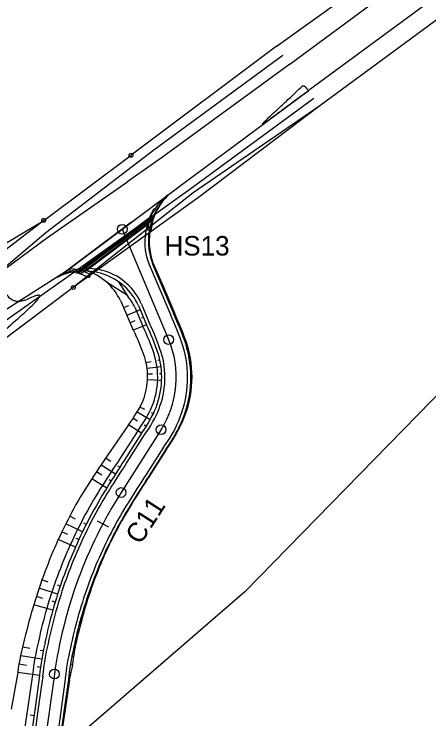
# Model space of a CAD drawing. Extents: x -495905 to -478420, y -1113297 to -1107716.
# Drawn here: x -481613 to -481549.1, y -1112614.7 to -1112506 of the extents above; entities that cross this region are included whole.
import ezdxf

# ---------------------------------------------------------------- set-up
doc = ezdxf.new("R2010")
doc.units = 0
for name, color, linetype in [('03_PC_OBJEKTY_STAV', 7, 'Continuous'), ('03_PC_POPIS_NÁVRH', 7, 'Continuous'), ('2D_VRSTEVNICE', 7, 'Continuous'), ('C11_HATCH_SLOPE_L', 7, 'Continuous'), ('C11_HATCH_SLOPE_R', 7, 'Continuous'), ('C11_HECTOMETRY', 7, 'Continuous'), ('C11_HLBODY', 7, 'Continuous'), ('C11_HRANA_TELESO', 7, 'Continuous'), ('C11_KORUNA', 7, 'Continuous'), ('C11_OSA', 7, 'Continuous'), ('C11_PRIKOP', 7, 'Continuous'), ('C11_STANICENI', 7, 'Continuous'), ('C11_VOZOVKA', 7, 'Continuous'), ('C11_ZPEVKRAJ', 7, 'Continuous'), ('křižovatky', 7, 'Continuous'), ('ODVODNĚNÍ PLOŠNÉ', 7, 'Continuous'), ('PLYN', 7, 'Continuous'), ('pomoc', 7, 'Continuous'), ('zamereni', 7, 'Continuous'), ('ŽLAB', 7, 'Continuous')]:
    doc.layers.add(name, color=color, linetype=linetype)

# ---------------------------------------------------------------- blocks, each defined once
blk = doc.blocks.new('A$C55D')
at = {"layer": 'ŽLAB'}
for p, q in [((-7.761, 0.901), (-8.121, 0.554)), ((-8.121, 0.554), (-7.1, -0.505)), ((-6.608, -0.294), (-7.761, 0.901)), ((-6.75, -0.147), (6.75, 0.147)), ((6.456, -0.009), (8.142, 0.887)), ((7.567, 0.015), (6.708, -0.004)), ((8.377, 0.446), (7.174, -0.193)), ((8.142, 0.887), (8.377, 0.446)), ((6.708, -0.004), (-7.289, -0.309)), ((7.174, -0.193), (-7.1, -0.505)), ((-7.1, -0.505), (-6.174, -1.981)), ((-6.976, -0.703), (6.971, -0.398)), ((-5.75, -1.715), (-6.394, -0.69)), ((6.098, -0.567), (-6.301, -0.838)), ((5.398, -1.272), (6.251, -0.414)), ((7.174, -0.193), (5.752, -1.625)), ((-6.174, -1.981), (-5.75, -1.715)), ((5.752, -1.625), (5.398, -1.272))]:
    blk.add_line(p, q, dxfattribs=at)

msp = doc.modelspace()

# ---------------------------------------------------------------- linework, layer by layer
at = {"layer": '2D_VRSTEVNICE'}
for points in [[(-481647.93, -1112548.5), (-481648.61, -1112547.68), (-481664.2, -1112542.72), (-481664.55, -1112542.45), (-481665.56, -1112541.98), (-481665.08, -1112541.52), (-481663.7, -1112539.31), (-481651.29, -1112540.7), (-481629.73, -1112529.7), (-481626.86, -1112529.87), (-481616.46, -1112498.69), (-481609.21, -1112494.2)], [(-481568.62, -1112517.17), (-481572.56, -1112520.9), (-481572.83, -1112521.09), (-481575.41, -1112523.59), (-481572.64, -1112521.55), (-481572.56, -1112521.5), (-481567.66, -1112517.89), (-481567.59, -1112517.97), (-481568.31, -1112516.94), (-481568.62, -1112517.17)], [(-481610.72, -1112549.89), (-481614.2, -1112551.56), (-481614.87, -1112546.89)], [(-481624.37, -1112563.28), (-481623.78, -1112562.56), (-481623.64, -1112562.53), (-481623.56, -1112562.46), (-481618.52, -1112558.17), (-481617.34, -1112557.32), (-481616.73, -1112556.77), (-481606.97, -1112548.11), (-481610.72, -1112549.89)]]:
    msp.add_open_spline(points, degree=2, dxfattribs=at)
at = {"layer": 'C11_HATCH_SLOPE_L'}
for p, q in [((-481589.91, -1112548.7), (-481589.84, -1112548.67)), ((-481589.77, -1112548.65), (-481589.77, -1112548.65)), ((-481589.42, -1112549.85), (-481589.28, -1112549.8)), ((-481588.93, -1112551.01), (-481588.86, -1112550.98)), ((-481588.79, -1112550.95), (-481588.79, -1112550.95)), ((-481588.45, -1112552.16), (-481588.3, -1112552.1)), ((-481586.14, -1112558.41), (-481586.05, -1112558.39)), ((-481585.96, -1112558.37), (-481585.96, -1112558.37)), ((-481585.9, -1112559.82), (-481585.72, -1112559.8)), ((-481585.78, -1112561.25), (-481585.69, -1112561.25)), ((-481585.6, -1112561.25), (-481585.6, -1112561.25)), ((-481585.77, -1112562.69), (-481585.59, -1112562.7)), ((-481587.51, -1112569.61), (-481587.47, -1112569.63)), ((-481587.42, -1112569.65), (-481587.42, -1112569.65)), ((-481588.2, -1112570.87), (-481588.12, -1112570.92)), ((-481588.9, -1112571.99), (-481588.86, -1112572.01)), ((-481588.83, -1112572.03), (-481588.83, -1112572.03)), ((-481589.57, -1112573.04), (-481589.51, -1112573.08)), ((-481592.92, -1112578.31), (-481592.9, -1112578.33)), ((-481592.88, -1112578.34), (-481592.88, -1112578.34)), ((-481593.59, -1112579.37), (-481593.54, -1112579.4)), ((-481594.27, -1112580.42), (-481594.24, -1112580.44)), ((-481594.21, -1112580.46), (-481594.21, -1112580.46)), ((-481594.92, -1112581.46), (-481594.87, -1112581.5)), ((-481597.9, -1112586.73), (-481597.86, -1112586.75)), ((-481597.82, -1112586.77), (-481597.82, -1112586.77)), ((-481598.43, -1112587.81), (-481598.35, -1112587.85)), ((-481598.95, -1112588.91), (-481598.91, -1112588.93)), ((-481598.86, -1112588.95), (-481598.86, -1112588.95)), ((-481599.45, -1112590.01), (-481599.36, -1112590.05)), ((-481601.64, -1112595.64), (-481601.58, -1112595.67)), ((-481601.51, -1112595.69), (-481601.51, -1112595.69)), ((-481602.02, -1112596.79), (-481601.88, -1112596.84)), ((-481602.38, -1112597.95), (-481602.3, -1112597.97)), ((-481602.23, -1112597.99), (-481602.23, -1112597.99)), ((-481602.71, -1112599.11), (-481602.55, -1112599.16)), ((-481604.08, -1112605), (-481603.99, -1112605.02)), ((-481603.9, -1112605.03), (-481603.9, -1112605.03)), ((-481604.29, -1112606.19), (-481604.11, -1112606.22)), ((-481604.48, -1112607.39), (-481604.39, -1112607.4)), ((-481604.31, -1112607.41), (-481604.31, -1112607.41)), ((-481604.65, -1112608.6), (-481604.48, -1112608.63))]:
    msp.add_line(p, q, dxfattribs=at)
at = {"layer": 'C11_HATCH_SLOPE_R'}
for p, q in [((-481595.39, -1112551.01), (-481596.14, -1112551.33)), ((-481593.57, -1112551.6), (-481595.64, -1112552.48)), ((-481594.4, -1112553.31), (-481595.14, -1112553.62)), ((-481593.08, -1112552.75), (-481593.37, -1112552.88)), ((-481592.6, -1112553.91), (-481594.64, -1112554.77)), ((-481591.91, -1112559.64), (-481592.67, -1112559.81)), ((-481590.54, -1112559.35), (-481590.84, -1112559.42)), ((-481590.36, -1112560.4), (-481592.52, -1112560.68)), ((-481591.67, -1112561.52), (-481592.44, -1112561.55)), ((-481590.27, -1112561.46), (-481590.58, -1112561.47)), ((-481590.27, -1112562.52), (-481592.44, -1112562.43)), ((-481592.87, -1112566.99), (-481593.61, -1112566.63)), ((-481592.06, -1112568.57), (-481594.06, -1112567.37)), ((-481591.55, -1112567.63), (-481591.85, -1112567.49)), ((-481593.97, -1112568.76), (-481594.69, -1112568.3)), ((-481593.36, -1112570.62), (-481595.39, -1112569.33)), ((-481592.69, -1112569.57), (-481592.97, -1112569.39)), ((-481598.12, -1112575), (-481598.91, -1112574.5)), ((-481597.39, -1112576.95), (-481599.61, -1112575.53)), ((-481596.72, -1112575.9), (-481597.03, -1112575.7)), ((-481599.51, -1112577.08), (-481600.32, -1112576.57)), ((-481598.74, -1112579.08), (-481601.04, -1112577.64)), ((-481598.06, -1112578.01), (-481598.38, -1112577.8)), ((-481603.55, -1112583.86), (-481604.45, -1112583.41)), ((-481602.48, -1112585.85), (-481605.06, -1112584.6)), ((-481601.91, -1112584.69), (-481602.28, -1112584.51)), ((-481604.73, -1112586.23), (-481605.65, -1112585.81)), ((-481603.57, -1112588.19), (-481606.21, -1112587.02)), ((-481603.04, -1112587.02), (-481603.43, -1112586.83)), ((-481607.76, -1112593.57), (-481608.73, -1112593.24)), ((-481606.31, -1112595.43), (-481609.17, -1112594.52)), ((-481605.9, -1112594.2), (-481606.35, -1112594.05)), ((-481608.6, -1112596.09), (-481609.59, -1112595.79)), ((-481607.05, -1112597.9), (-481609.98, -1112597.08)), ((-481606.69, -1112596.66), (-481607.15, -1112596.52)), ((-481610.61, -1112603.79), (-481611.7, -1112603.59)), ((-481608.5, -1112604.18), (-481609.02, -1112604.09)), ((-481608.73, -1112605.45), (-481611.98, -1112604.91)), ((-481611.11, -1112606.4), (-481612.24, -1112606.23)), ((-481608.93, -1112606.73), (-481609.46, -1112606.65)), ((-481609.11, -1112607.99), (-481612.47, -1112607.52)), ((-481609.97, -1112614.18), (-481610.53, -1112614.1))]:
    msp.add_line(p, q, dxfattribs=at)
at = {"layer": 'C11_HECTOMETRY'}
msp.add_circle((-481596.35, -1112539.21), 0.75, dxfattribs=at)
at = {"layer": 'C11_HLBODY'}
for centre in [(-481596.35, -1112539.21), (-481589.19, -1112556.2), (-481590.35, -1112570.08), (-481596.52, -1112579.77), (-481606.8, -1112607.75)]:
    msp.add_circle(centre, 0.75, dxfattribs=at)
at = {"layer": 'C11_HRANA_TELESO'}
for p, q in [((-481591.61, -1112544.39), (-481590.26, -1112547.5)), ((-481590.26, -1112547.5), (-481588.3, -1112552.1)), ((-481596.64, -1112550.19), (-481594.64, -1112554.77)), ((-481595.39, -1112569.33), (-481598.21, -1112573.47)), ((-481589.51, -1112573.08), (-481592.21, -1112577.29)), ((-481612.47, -1112607.52), (-481613.47, -1112613.17)), ((-481604.48, -1112608.63), (-481605.22, -1112613.57)), ((-481605.22, -1112613.57), (-481605.97, -1112618.52))]:
    msp.add_line(p, q, dxfattribs=at)
for centre, radius, start, end in [((-481635.7, -1112574.24), 52.31, 19.2892, 25.0421), ((-481622.96, -1112569.07), 31.74, 18.596, 26.7972), ((-481603.01, -1112562), 17.43, 357.7019, 16.8005), ((-481603.01, -1112562.01), 10.58, 357.7209, 16.8195), ((-481602.96, -1112561.8), 10.53, 337.4632, 356.5663), ((-481602.97, -1112561.84), 17.39, 338.0666, 357.1664), ((-481612.19, -1112556.53), 21.12, 322.6878, 333.8488), ((-481608.69, -1112559.14), 23.71, 323.9962, 337.187), ((-481413.38, -1112701.54), 224.87, 145.2801, 146.5653), ((-481421.87, -1112687.79), 203.05, 147.0267, 148.4322), ((-481538.33, -1112618.82), 75.02, 146.7075, 150.8011), ((-481537.35, -1112617.15), 67.67, 148.2076, 152.3001), ((-481537.86, -1112618.17), 75.11, 151.4122, 155.505), ((-481537.37, -1112617.16), 67.66, 152.2813, 156.3739), ((-481537.85, -1112618.3), 75.18, 155.4194, 159.5123), ((-481537.34, -1112617.03), 67.64, 156.4907, 160.5833), ((-481537.81, -1112618.42), 75.26, 159.4297, 163.5227), ((-481537.29, -1112616.8), 67.6, 160.7759, 164.8686), ((-481538.03, -1112619.55), 75.38, 162.6591, 166.7535), ((-481537.4, -1112617.09), 67.57, 164.6097, 168.7023), ((-481575.06, -1112612.42), 37.73, 164.4045, 172.5431), ((-481637.28, -1112600.54), 33.78, 346.1579, 354.3818)]:
    msp.add_arc(centre, radius, start, end, dxfattribs=at)
at = {"layer": 'C11_KORUNA'}
for p, q in [((-481591.71, -1112544.43), (-481590.39, -1112547.55)), ((-481590.39, -1112547.55), (-481588.45, -1112552.16)), ((-481593.84, -1112550.96), (-481592.6, -1112553.91)), ((-481593.36, -1112570.62), (-481596.05, -1112574.84)), ((-481589.57, -1112573.04), (-481592.25, -1112577.26)), ((-481609.11, -1112607.99), (-481609.79, -1112612.94)), ((-481604.65, -1112608.6), (-481605.34, -1112613.56)), ((-481609.79, -1112612.94), (-481610.48, -1112617.89)), ((-481605.34, -1112613.56), (-481606.02, -1112618.51))]:
    msp.add_line(p, q, dxfattribs=at)
for centre, radius, start, end in [((-481635.45, -1112573.81), 51.75, 18.9449, 24.7394), ((-481627.09, -1112570.44), 38.25, 18.4635, 25.6048), ((-481603.01, -1112562.03), 17.25, 357.8093, 16.9079), ((-481603.01, -1112562.03), 12.75, 357.8093, 16.9079), ((-481603.01, -1112562.03), 12.75, 338.7107, 357.8093), ((-481603.01, -1112562.03), 17.25, 338.7107, 357.8093), ((-481609.78, -1112558.75), 20.26, 324.1239, 337.0248), ((-481609.49, -1112558.88), 24.44, 324.6101, 337.3601), ((-481414.5, -1112693.25), 216.75, 146.8885, 148.2152), ((-481422.09, -1112688.41), 203.25, 146.8481, 148.2523), ((-481537.47, -1112617.36), 72.25, 148.0062, 152.0987), ((-481537.47, -1112617.36), 67.75, 148.0062, 152.0987), ((-481537.47, -1112617.36), 72.25, 152.0987, 156.1913), ((-481537.47, -1112617.36), 67.75, 152.0987, 156.1913), ((-481537.47, -1112617.36), 72.25, 156.1913, 160.2839), ((-481537.47, -1112617.36), 67.75, 156.1913, 160.2839), ((-481537.47, -1112617.36), 72.25, 160.2839, 164.3764), ((-481537.47, -1112617.36), 67.75, 160.2839, 164.3764), ((-481537.47, -1112617.36), 72.25, 164.3764, 168.469), ((-481537.47, -1112617.36), 67.75, 164.3764, 168.469), ((-481573.14, -1112611.41), 36.12, 166.4039, 174.5664), ((-481570.92, -1112611.79), 33.88, 166.3865, 174.6067)]:
    msp.add_arc(centre, radius, start, end, dxfattribs=at)
at = {"layer": 'C11_OSA'}
for p, q in [((-481596.35, -1112539.21), (-481589.19, -1112556.2)), ((-481590.35, -1112570.08), (-481596.52, -1112579.77)), ((-481606.8, -1112607.75), (-481611.15, -1112639.14))]:
    msp.add_line(p, q, dxfattribs=at)
for centre, radius, start, end in [((-481603.01, -1112562.03), 15, 327.5225, 22.8611), ((-481537.47, -1112617.36), 70, 147.5225, 172.1135)]:
    msp.add_arc(centre, radius, start, end, dxfattribs=at)
at = {"layer": 'C11_PRIKOP'}
for p, q in [((-481594.41, -1112551.22), (-481593.17, -1112554.15)), ((-481593.93, -1112570.26), (-481596.65, -1112574.46)), ((-481610.17, -1112607.84), (-481610.91, -1112612.78)), ((-481610.91, -1112612.78), (-481611.65, -1112617.73))]:
    msp.add_line(p, q, dxfattribs=at)
for centre, radius, start, end in [((-481625.94, -1112570.01), 36.41, 18.425, 25.8268), ((-481603.01, -1112562.01), 12.13, 357.7063, 16.8049), ((-481602.99, -1112561.97), 12.12, 338.4317, 357.5305), ((-481611.06, -1112557.85), 21.15, 324.0807, 336.0878), ((-481414.39, -1112695.98), 219.06, 146.3067, 147.6212), ((-481537.83, -1112617.98), 73.04, 147.4396, 151.5324), ((-481537.78, -1112618.01), 73.1, 151.5328, 155.6255), ((-481537.74, -1112618.03), 73.15, 155.6254, 159.7181), ((-481537.69, -1112618.04), 73.2, 159.7188, 163.8116), ((-481537.64, -1112618.06), 73.25, 163.8113, 167.9041), ((-481573.74, -1112611.67), 36.64, 165.8389, 173.9919)]:
    msp.add_arc(centre, radius, start, end, dxfattribs=at)
at = {"layer": 'C11_STANICENI'}
msp.add_line((-481600.21, -1112584.13), (-481598.45, -1112585.07), dxfattribs=at)
at = {"layer": 'C11_VOZOVKA'}
for p, q in [((-481592.17, -1112544.62), (-481590.85, -1112547.75)), ((-481590.85, -1112547.75), (-481588.91, -1112552.35)), ((-481592.94, -1112570.89), (-481595.63, -1112575.11)), ((-481589.99, -1112572.77), (-481592.67, -1112576.99)), ((-481608.61, -1112608.05), (-481609.3, -1112613.01)), ((-481605.15, -1112608.53), (-481605.83, -1112613.49)), ((-481609.3, -1112613.01), (-481609.98, -1112617.96)), ((-481605.83, -1112613.49), (-481606.52, -1112618.44))]:
    msp.add_line(p, q, dxfattribs=at)
for centre, radius, start, end in [((-481634.52, -1112573.44), 50.25, 18.9076, 24.816), ((-481628.02, -1112570.81), 39.75, 18.5378, 25.4842), ((-481603.01, -1112562.03), 16.75, 357.8093, 16.9079), ((-481603.01, -1112562.03), 13.25, 357.8093, 16.9079), ((-481603.01, -1112562.03), 13.25, 338.7107, 357.8093), ((-481603.01, -1112562.03), 16.75, 338.7107, 357.8093), ((-481606.57, -1112560.55), 17.11, 322.8183, 338.4369), ((-481604.7, -1112561.55), 18.51, 322.6659, 339.2264), ((-481415.34, -1112692.71), 215.25, 146.8842, 148.2191), ((-481421.24, -1112688.95), 204.75, 146.8529, 148.2479), ((-481537.47, -1112617.36), 71.75, 148.0062, 152.0987), ((-481537.47, -1112617.36), 68.25, 148.0062, 152.0987), ((-481537.47, -1112617.36), 71.75, 152.0987, 156.1913), ((-481537.47, -1112617.36), 68.25, 152.0987, 156.1913), ((-481537.47, -1112617.36), 71.75, 156.1913, 160.2839), ((-481537.47, -1112617.36), 68.25, 156.1913, 160.2839), ((-481537.47, -1112617.36), 71.75, 160.2839, 164.3764), ((-481537.47, -1112617.36), 68.25, 160.2839, 164.3764), ((-481537.47, -1112617.36), 71.75, 164.3764, 168.469), ((-481537.47, -1112617.36), 68.25, 164.3764, 168.469), ((-481572.9, -1112611.45), 35.88, 166.4021, 174.5707), ((-481571.17, -1112611.74), 34.12, 166.3885, 174.602)]:
    msp.add_arc(centre, radius, start, end, dxfattribs=at)
at = {"layer": 'C11_ZPEVKRAJ'}
for p, q in [((-481590.85, -1112547.75), (-481588.91, -1112552.35)), ((-481593.38, -1112550.76), (-481592.14, -1112553.71)), ((-481592.94, -1112570.89), (-481595.63, -1112575.11)), ((-481589.99, -1112572.77), (-481592.67, -1112576.99)), ((-481608.61, -1112608.05), (-481609.3, -1112613.01)), ((-481605.15, -1112608.53), (-481605.83, -1112613.49)), ((-481609.3, -1112613.01), (-481609.98, -1112617.96)), ((-481605.83, -1112613.49), (-481606.52, -1112618.44))]:
    msp.add_line(p, q, dxfattribs=at)
for centre, radius, start, end in [((-481634.52, -1112573.44), 50.25, 18.9076, 24.816), ((-481628.02, -1112570.81), 39.75, 18.5378, 25.4842), ((-481603.01, -1112562.03), 16.75, 357.8093, 16.9079), ((-481603.01, -1112562.03), 13.25, 357.8093, 16.9079), ((-481603.01, -1112562.03), 13.25, 338.7107, 357.8093), ((-481603.01, -1112562.03), 16.75, 338.7107, 357.8093), ((-481606.57, -1112560.55), 17.11, 322.8183, 338.4369), ((-481604.7, -1112561.55), 18.51, 322.6659, 339.2264), ((-481415.34, -1112692.71), 215.25, 146.8842, 148.2191), ((-481421.24, -1112688.95), 204.75, 146.8529, 148.2479), ((-481537.47, -1112617.36), 71.75, 148.0062, 152.0987), ((-481537.47, -1112617.36), 68.25, 148.0062, 152.0987), ((-481537.47, -1112617.36), 71.75, 152.0987, 156.1913), ((-481537.47, -1112617.36), 68.25, 152.0987, 156.1913), ((-481537.47, -1112617.36), 71.75, 156.1913, 160.2839), ((-481537.47, -1112617.36), 68.25, 156.1913, 160.2839), ((-481537.47, -1112617.36), 71.75, 160.2839, 164.3764), ((-481537.47, -1112617.36), 68.25, 160.2839, 164.3764), ((-481537.47, -1112617.36), 71.75, 164.3764, 168.469), ((-481537.47, -1112617.36), 68.25, 164.3764, 168.469), ((-481572.9, -1112611.45), 35.88, 166.4021, 174.5707), ((-481571.17, -1112611.74), 34.12, 166.3885, 174.602)]:
    msp.add_arc(centre, radius, start, end, dxfattribs=at)
at = {"layer": 'křižovatky'}
for q in [(-481598.75, -1112547.36), (-481596.87, -1112547.32)]:
    msp.add_line((-481595.54, -1112549.43), q, dxfattribs=at)
for centre, radius, start, end in [((-481601.67, -1112554.26), 9, 22.8611, 122.4451), ((-481602.22, -1112554.87), 9.25, 25.0005, 117.5387), ((-481604.45, -1112553.83), 8.62, 25.0005, 72.1749), ((-481602.22, -1112554.87), 8.62, 25.0005, 39.1008)]:
    msp.add_arc(centre, radius, start, end, dxfattribs=at)
at = {"layer": 'ODVODNĚNÍ PLOŠNÉ'}
for points in [[(-481364.04, -1112717.86), (-481405.4, -1112669.63), (-481439.96, -1112636.43), (-481462.48, -1112600.66), (-481486.72, -1112576.78), (-481511.21, -1112532.78), (-481541.96, -1112558.79), (-481577.43, -1112595.06)], [(-481577.43, -1112595.06), (-481612.93, -1112625.72), (-481606.02, -1112677.17), (-481582.37, -1112709.93)]]:
    msp.add_lwpolyline(points, dxfattribs=at)
at = {"layer": 'pomoc'}
for p, q in [((-481594.91, -1112538.13), (-481589.26, -1112533.91)), ((-481594.91, -1112538.13), (-481605.19, -1112545.83)), ((-481605.19, -1112545.83), (-481606.5, -1112546.66))]:
    msp.add_line(p, q, dxfattribs=at)
for centre, radius, start, end in [((-481583.88, -1112541.13), 9, 126.7207, 202.8611), ((-481582.49, -1112541.03), 9.82, 133.5438, 200.2162), ((-481582.14, -1112541.01), 10.05, 135.0506, 199.6521)]:
    msp.add_arc(centre, radius, start, end, dxfattribs=at)
at = {"layer": 'zamereni'}
for p, q in [((-481572.61, -1112511.06), (-481489.7, -1112450.86)), ((-481570.48, -1112513.76), (-481489.21, -1112453.51)), ((-481485.46, -1112457.52), (-481567.69, -1112517.85)), ((-481485.03, -1112460.77), (-481565.86, -1112520.18)), ((-481572.61, -1112511.06), (-481594.99, -1112527.8)), ((-481591.46, -1112526.94), (-481571.59, -1112512.38)), ((-481570.48, -1112513.76), (-481590.14, -1112528.09)), ((-481586.98, -1112532.19), (-481567.69, -1112517.85)), ((-481566.8, -1112519.06), (-481585.9, -1112533.07)), ((-481565.86, -1112520.18), (-481585.43, -1112533.61)), ((-481565.86, -1112520.18), (-481584.58, -1112534.31)), ((-481608.12, -1112539.69), (-481591.46, -1112526.94)), ((-481608.46, -1112537.83), (-481594.99, -1112527.8)), ((-481590.14, -1112528.09), (-481595.46, -1112531.85)), ((-481608.01, -1112540.57), (-481595.46, -1112531.85)), ((-481605.19, -1112545.83), (-481586.98, -1112532.19)), ((-481585.9, -1112533.07), (-481604.87, -1112546.64)), ((-481585.43, -1112533.61), (-481603.89, -1112548.18)), ((-481584.58, -1112534.31), (-481603.89, -1112548.18)), ((-481627.86, -1112549.48), (-481608.46, -1112537.83)), ((-481608.46, -1112537.83), (-481617.67, -1112544.95)), ((-481616.42, -1112546.71), (-481608.12, -1112539.69)), ((-481616.42, -1112546.71), (-481608.01, -1112540.57)), ((-481605.19, -1112545.83), (-481619.41, -1112554.87)), ((-481604.87, -1112546.64), (-481618.58, -1112556.27)), ((-481603.89, -1112548.18), (-481616.76, -1112557.81))]:
    msp.add_line(p, q, dxfattribs=at)
for centre in [(-481594.99, -1112527.8), (-481608.46, -1112537.83), (-481603.89, -1112548.18)]:
    msp.add_circle(centre, 0.3, dxfattribs=at)

# ---------------------------------------------------------------- block references
at = {"layer": 'PLYN', "rotation": 35.57765689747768}
msp.add_blockref('A$C55D', (-481597.54, -1112541.45), dxfattribs=at)

# ---------------------------------------------------------------- texts
at = {"layer": '03_PC_OBJEKTY_STAV'}
msp.add_text('HS13', height=3, dxfattribs=at).set_placement((-481589.83, -1112543.25))
at = {"layer": '03_PC_POPIS_NÁVRH'}
msp.add_text('C11', height=3, rotation=57.2675, dxfattribs=at).set_placement((-481593.54, -1112587.94))

doc.saveas('drawing.dxf')
